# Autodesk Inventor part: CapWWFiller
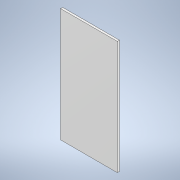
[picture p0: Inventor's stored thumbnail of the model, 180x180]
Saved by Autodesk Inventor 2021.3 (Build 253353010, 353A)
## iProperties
Created: 2021-11
Part Number: CapWWFiller
Material: Polystyrene, High Impact
Document SubType Name: Modeling
Designer: u1426
Density: 1.022 g/cm^3
Appearance: Smooth - White
Author: u1426
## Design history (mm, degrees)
sketch "Sketch1"
  geometry: L1 (0, 0)-(508, 0); L2 (508, 0)-(508, 1016); L3 (508, 1016)-(0, 1016); L4 (0, 1016)-(0, 0)
  constraints: 8 end point, 2 parallel, 1 horizontal, 1 perpendicular
  dimensions: "d0" = 508 distance of L2.end L3.end; "d1" = 1016 distance of L1.end L2.end
extrude "Extrusion1" new body sketch "Sketch1" distance "d2" = 19.05; taper "d3" = 0 deg
body "Solid1"
